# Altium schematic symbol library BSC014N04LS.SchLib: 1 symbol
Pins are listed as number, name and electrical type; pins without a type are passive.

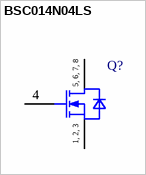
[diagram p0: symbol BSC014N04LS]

## BSC014N04LS
designator Q?  (value not drawn)
OptiMOS Power - MOSFET, 40 V; Manufacturer: Infineon Technologies
footprint INF-PG-TDSON-8-FL
pins: 1 SOURCE, 2 SOURCE, 3 SOURCE, 4 GATE, 5 DRAIN, 6 DRAIN, 7 DRAIN, 8 DRAIN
